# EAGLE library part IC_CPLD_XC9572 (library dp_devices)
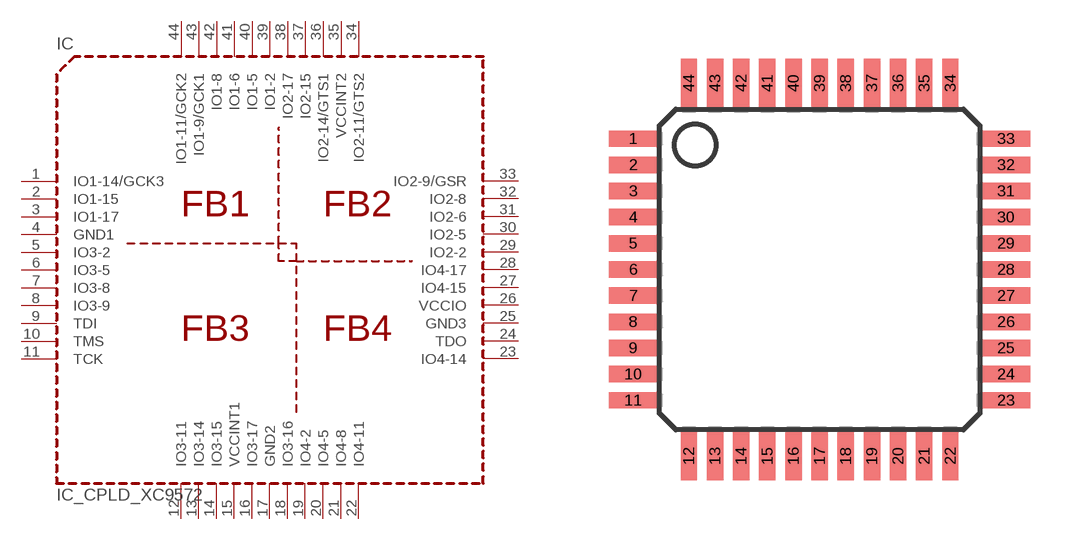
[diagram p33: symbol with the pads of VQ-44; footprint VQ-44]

Designator prefix IC

## IC_CPLD_XC9572VQ44  [VQ-44]
1  IO1-14/GCK3
2  IO1-15
3  IO1-17
4  GND1
5  IO3-2
6  IO3-5
7  IO3-8
8  IO3-9
9  TDI
10  TMS
11  TCK
12  IO3-11
13  IO3-14
14  IO3-15
15  VCCINT1
16  IO3-17
17  GND2
18  IO3-16
19  IO4-2
20  IO4-5
21  IO4-8
22  IO4-11
23  IO4-14
24  TDO
25  GND3
26  VCCIO
27  IO4-15
28  IO4-17
29  IO2-2
30  IO2-5
31  IO2-6
32  IO2-8
33  IO2-9/GSR
34  IO2-11/GTS2
35  VCCINT2
36  IO2-14/GTS1
37  IO2-15
38  IO2-17
39  IO1-2
40  IO1-5
41  IO1-6
42  IO1-8
43  IO1-9/GCK1
44  IO1-11/GCK2

## Footprint VQ-44 (pad centres in mm)
smd 1.5 x 0.5: 1 -5.7,4; 2 -5.7,3.2; 3 -5.7,2.4; 4 -5.7,1.6; 5 -5.7,0.8; 6 -5.7,0; 7 -5.7,-0.8; 8 -5.7,-1.6; 9 -5.7,-2.4; 10 -5.7,-3.2; 11 -5.7,-4; 23 5.7,-4; 24 5.7,-3.2; 25 5.7,-2.4; 26 5.7,-1.6; 27 5.7,-0.8; 28 5.7,0; 29 5.7,0.8; 30 5.7,1.6; 31 5.7,2.4; 32 5.7,3.2; 33 5.7,4
smd 0.5 x 1.5: 12 -4,-5.7; 13 -3.2,-5.7; 14 -2.4,-5.7; 15 -1.6,-5.7; 16 -0.8,-5.7; 17 0,-5.7; 18 0.8,-5.7; 19 1.6,-5.7; 20 2.4,-5.7; 21 3.2,-5.7; 22 4,-5.7; 34 4,5.7; 35 3.2,5.7; 36 2.4,5.7; 37 1.6,5.7; 38 0.8,5.7; 39 0,5.7; 40 -0.8,5.7; 41 -1.6,5.7; 42 -2.4,5.7; 43 -3.2,5.7; 44 -4,5.7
